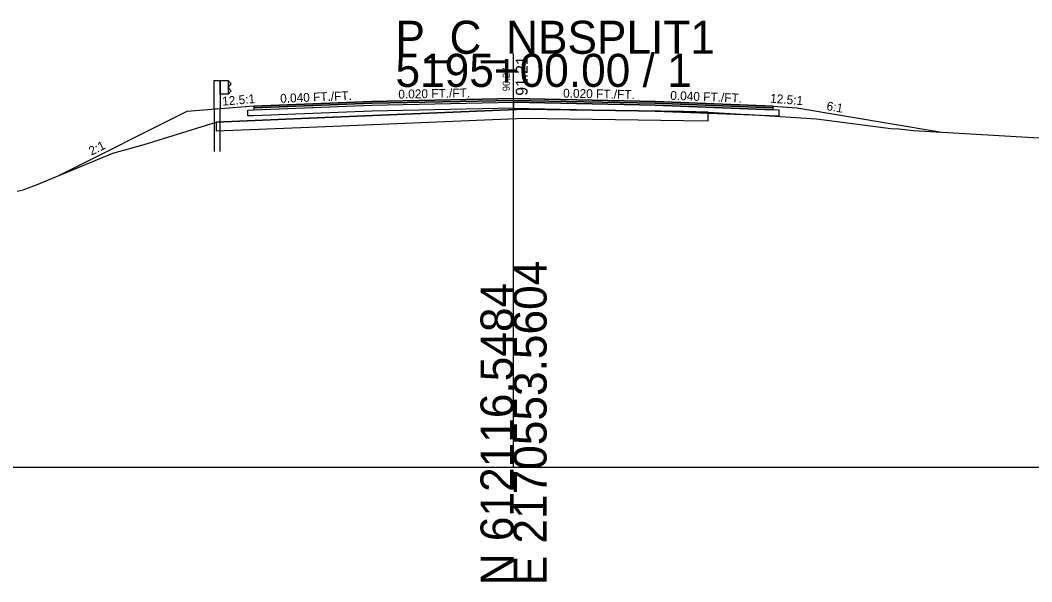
# Model space of a CAD drawing. Extents: x -26 to 1303, y -3010 to 12038.
# Drawn here: x 108.2 to 193.9, y 10990.3 to 11037.8 of the extents above; entities that cross this region are included whole.
import ezdxf

# ---------------------------------------------------------------- set-up
doc = ezdxf.new("R2010")
doc.units = 0
for name, color, linetype in [('RD_GPK_XS_Cell', 7, 'Continuous'), ('RD_PD_Final_TrvlWay', 7, 'Continuous'), ('RD_XS_Base', 7, 'Continuous'), ('RD_XS_ExGround', 7, 'Continuous'), ('RD_XS_ExPaveRet', 7, 'Continuous'), ('RD_XS_GR', 7, 'Continuous'), ('RD_XS_Greenside', 7, 'Continuous'), ('RD_XS_Pave', 7, 'Continuous'), ('RD_XS_PaveOvlay_CP', 7, 'Continuous'), ('RD_XS_TieSlope', 7, 'Continuous'), ('RD_XS_TX_Elev_EX', 7, 'Continuous'), ('RD_XS_TX_Elev_PR', 7, 'Continuous'), ('RD_XS_TX_ShdSlope', 7, 'Continuous'), ('RD_XS_TX_Slope', 7, 'Continuous')]:
    doc.layers.add(name, color=color, linetype=linetype)

msp = doc.modelspace()

# ---------------------------------------------------------------- linework, layer by layer
at = {"layer": 'RD_GPK_XS_Cell'}
for p, q in [((150, 11000), (150, 11035)), ((0, 11000), (150, 11000)), ((150, 11000), (300, 11000))]:
    msp.add_line(p, q, dxfattribs=at)
at = {"layer": 'RD_PD_Final_TrvlWay'}
for p, q in [((125.153, 11030.346), (124.653, 11030.306)), ((124.653, 11030.306), (124.653, 11026.741)), ((125.153, 11026.741), (125.153, 11030.346))]:
    msp.add_line(p, q, dxfattribs=at)
at = {"layer": 'RD_XS_Base'}
for p, q in [((128, 11030.256), (138, 11030.656)), ((138, 11030.656), (150, 11030.896)), ((138, 11030.656), (138, 11030.656)), ((150, 11030.896), (150, 11031.055)), ((150, 11031.055), (150, 11030.396)), ((150, 11030.896), (150, 11030.396)), ((162, 11030.656), (150, 11030.896)), ((150, 11030.896), (150, 11030.896)), ((172, 11030.256), (162, 11030.656)), ((164, 11030.576), (164, 11030.576)), ((127.5, 11030.236), (128, 11030.256)), ((127.5, 11029.736), (127.5, 11030.236)), ((127.5, 11030.236), (127.5, 11030.236)), ((128, 11029.756), (127.5, 11029.736)), ((127.5, 11029.736), (127.5, 11029.736)), ((127.5, 11029.736), (127.5, 11029.736)), ((128, 11030.256), (128, 11030.256)), ((138, 11030.156), (128, 11029.756)), ((128, 11029.756), (128, 11029.756)), ((150, 11030.396), (138, 11030.156)), ((138, 11030.156), (138, 11030.156)), ((150, 11030.396), (150, 11030.396)), ((150, 11030.396), (150, 11030.396)), ((150, 11030.396), (162, 11030.156)), ((162, 11030.156), (172.5, 11029.736)), ((164, 11030.076), (164, 11030.076)), ((172.5, 11030.236), (172, 11030.256)), ((172, 11030.256), (172, 11030.256)), ((172.5, 11029.736), (172.5, 11030.236)), ((172.5, 11030.236), (172.5, 11030.236)), ((172.5, 11029.736), (172.5, 11029.736)), ((172.5, 11029.736), (172.5, 11029.736))]:
    msp.add_line(p, q, dxfattribs=at)
at = {"layer": 'RD_XS_ExGround'}
msp.add_lwpolyline([(107.952, 11023.375), (108.464, 11023.475), (109.603, 11023.916), (116.06, 11026.588), (118.723, 11027.329), (124.825, 11029.22), (132.698, 11029.542), (150.914, 11030.306), (164.401, 11030.105), (166.475, 11030.072), (169.242, 11029.903), (169.955, 11029.866), (175.66, 11029.491), (181.957, 11028.683), (182.641, 11028.658), (183.884, 11028.511), (199.826, 11027.569)], dxfattribs=at)
at = {"layer": 'RD_XS_ExPaveRet'}
for points in [[(166.475, 11030.072), (164.401, 11030.105), (164.401, 11030.105), (150.914, 11030.306), (150.914, 11030.306), (132.698, 11029.542), (132.698, 11029.542), (124.825, 11029.221), (124.825, 11029.221), (124.825, 11028.47), (132.698, 11028.792), (132.698, 11028.792), (150.914, 11029.556), (150.914, 11029.556), (164.401, 11029.355), (164.401, 11029.355), (166.475, 11029.322), (166.475, 11029.322), (166.475, 11030.072), (166.475, 11030.072), (166.475, 11030.072)], [(164.401, 11030.105), (150.914, 11030.306), (132.698, 11029.542), (124.825, 11029.221)], [(124.825, 11029.221), (124.825, 11028.47), (132.698, 11028.792), (150.914, 11029.556), (164.401, 11029.355), (166.475, 11029.322), (166.475, 11029.322), (166.475, 11030.072)], [(166.475, 11030.072), (166.475, 11030.072), (164.401, 11030.105)]]:
    msp.add_lwpolyline(points, dxfattribs=at)
at = {"layer": 'RD_XS_GR'}
for points in [[(125.153, 11032.741), (125.153, 11030.346), (124.653, 11030.306), (124.653, 11032.741), (124.903, 11032.741), (125.153, 11032.741)], [(125.82, 11032.741), (125.82, 11031.575), (125.153, 11031.575), (125.153, 11032.741), (125.82, 11032.741)], [(126.091, 11032.45), (125.82, 11032.741), (125.82, 11031.575), (125.82, 11031.575), (125.82, 11031.575), (126.091, 11031.866), (126.091, 11031.866), (125.82, 11032.158), (125.82, 11032.158), (126.091, 11032.45), (126.091, 11032.45)]]:
    msp.add_lwpolyline(points, dxfattribs=at)
at = {"layer": 'RD_XS_Greenside'}
for p, q in [((122.341, 11030.121), (111.502, 11024.702)), ((174, 11030.414), (186.265, 11028.37))]:
    msp.add_line(p, q, dxfattribs=at)
at = {"layer": 'RD_XS_Pave'}
for p, q in [((138, 11030.974), (128, 11030.574)), ((138, 11030.815), (128, 11030.415)), ((128, 11030.415), (138, 11030.815)), ((128, 11030.256), (138, 11030.656)), ((128, 11030.574), (128, 11030.574)), ((128, 11030.574), (128, 11030.415)), ((150, 11031.214), (138, 11030.974)), ((150, 11031.055), (138, 11030.815)), ((138, 11030.815), (150, 11031.055)), ((138, 11030.974), (138, 11030.974)), ((138, 11030.656), (150, 11030.896)), ((138, 11030.815), (138, 11030.815)), ((138, 11030.815), (138, 11030.815)), ((138, 11030.656), (138, 11030.656)), ((162, 11030.974), (150, 11031.214)), ((150, 11030.896), (150, 11031.055)), ((150, 11031.055), (162, 11030.815)), ((162, 11030.815), (150, 11031.055)), ((150, 11031.055), (150, 11030.896)), ((150, 11030.896), (150, 11030.896)), ((150, 11030.896), (150, 11030.896)), ((150, 11030.896), (162, 11030.656)), ((172, 11030.574), (162, 11030.974)), ((162, 11030.815), (172, 11030.415)), ((172, 11030.415), (162, 11030.815)), ((162, 11030.656), (172, 11030.256)), ((164, 11030.894), (164, 11030.894)), ((164, 11030.735), (164, 11030.735)), ((164, 11030.735), (164, 11030.735)), ((164, 11030.576), (164, 11030.576)), ((172, 11030.415), (172, 11030.574)), ((172, 11030.574), (172, 11030.574)), ((128, 11030.415), (128, 11030.415)), ((128, 11030.415), (128, 11030.256)), ((128, 11030.415), (128, 11030.415)), ((128, 11030.415), (128, 11030.415)), ((128, 11030.256), (128, 11030.256)), ((128, 11030.256), (128, 11030.256)), ((172, 11030.415), (172, 11030.415)), ((172, 11030.415), (172, 11030.415)), ((172, 11030.256), (172, 11030.415)), ((172, 11030.415), (172, 11030.415)), ((172, 11030.256), (172, 11030.256)), ((172, 11030.256), (172, 11030.256))]:
    msp.add_line(p, q, dxfattribs=at)
at = {"layer": 'RD_XS_PaveOvlay_CP'}
for p, q in [((128, 11030.574), (138, 11030.974)), ((138, 11030.974), (150, 11031.214)), ((150, 11031.214), (162, 11030.974)), ((162, 11030.974), (172, 11030.574))]:
    msp.add_line(p, q, dxfattribs=at)
at = {"layer": 'RD_XS_TieSlope'}
for p, q in [((128, 11030.574), (122.341, 11030.121)), ((172, 11030.574), (174, 11030.414))]:
    msp.add_line(p, q, dxfattribs=at)

# ---------------------------------------------------------------- texts
at = {"layer": 'RD_GPK_XS_Cell'}
for s, p in [('P_C_NBSPLIT1', (140, 11035)), ('5195+00.00 / 1', (140, 11032.2))]:
    msp.add_text(s, height=2.8, dxfattribs=at).set_placement(p)
for s, p in [('E 2170553.5604', (152.8, 10990)), ('N 612116.5484', (150, 10990))]:
    msp.add_text(s, height=2.8, rotation=90, dxfattribs=at).set_placement(p)
at = {"layer": 'RD_XS_TX_Elev_EX'}
msp.add_text('90.27', height=0.6, rotation=90, dxfattribs=at).set_placement((149.674, 11031.829))
at = {"layer": 'RD_XS_TX_Elev_PR'}
msp.add_text('91.21', height=1, rotation=90, dxfattribs=at).set_placement((151.187, 11031.445))
at = {"layer": 'RD_XS_TX_ShdSlope'}
for rotation, p in [(4.57392, (125.35, 11030.61)), (355.42608, (171.711, 11030.871))]:
    msp.add_text('12.5:1', height=0.75, rotation=rotation, dxfattribs=at).set_placement(p)
at = {"layer": 'RD_XS_TX_Slope'}
for s, rotation, p in [('0.040 FT./FT.', 2.29061, (130.247, 11030.849)), ('0.020 FT./FT.', 1.14576, (140.248, 11031.204)), ('0.020 FT./FT.', 358.85424, (154.191, 11031.296)), ('0.040 FT./FT.', 357.70939, (163.262, 11031.109)), ('6:1', 350.53768, (176.464, 11030.237)), ('2:1', 26.56505, (114.249, 11026.371))]:
    msp.add_text(s, height=0.75, rotation=rotation, dxfattribs=at).set_placement(p)

doc.saveas('drawing.dxf')
